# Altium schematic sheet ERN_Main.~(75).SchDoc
size A; SheetNumber: 1; SheetTotal: 4; SPICEModelCacheDBTNACQE: <root> / <DocumentId>DBTNACQE</DocumentId> / </root>
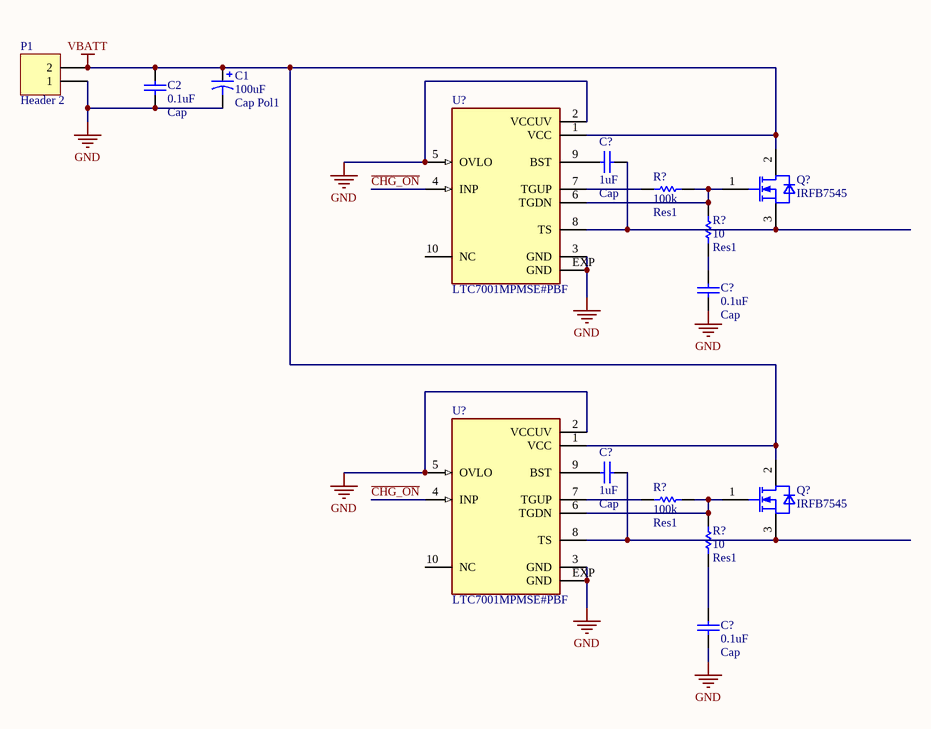
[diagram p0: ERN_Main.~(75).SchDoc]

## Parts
(Parts that share a designator on the sheet are numbered #1, #2 ... from top to bottom, then left to right.)
C1  Cap Pol1  value 100uF  [RB7.6-15]
C2  Cap  value 0.1uF  [RAD-0.3]
C?#1  Cap  value 1uF  [RAD-0.3]
C?#2  Cap  value 0.1uF  [RAD-0.3]
C?#3  Cap  value 1uF  [RAD-0.3]
C?#4  Cap  value 0.1uF  [RAD-0.3]
P1  Header 2  [HDR1X2]
Q?#1  IRFB7545  [IFX-PG-TO220-3-904]
Q?#2  IRFB7545  [IFX-PG-TO220-3-904]
R?#1  Res1  value 100k  [AXIAL-0.3]
R?#2  Res1  value 10  [AXIAL-0.3]
R?#3  Res1  value 100k  [AXIAL-0.3]
R?#4  Res1  value 10  [AXIAL-0.3]
U?#1  LTC7001MPMSE#PBF  [SOP50P490X110-11N]
U?#2  LTC7001MPMSE#PBF  [SOP50P490X110-11N]

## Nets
GND: C1.2 C2.1 C?#2.2 C?#4.2 P1.1 U?#1.2(VCCUV) U?#1.3(GND) U?#1.5(OVLO) U?#1.EXP(GND) U?#2.2(VCCUV) U?#2.3(GND) U?#2.5(OVLO) U?#2.EXP(GND)
VBATT: C1.1 C2.2 P1.2 Q?#1.2(DRAIN) Q?#2.2(DRAIN) U?#1.1(VCC) U?#2.1(VCC)
~{CHG_ON}: U?#1.4(INP) U?#2.4(INP)
NetC?#1_1: C?#1.1 Q?#1.3(SOURCE) U?#1.8(TS)
NetC?#1_2: C?#1.2 U?#1.9(BST)
NetC?#2_1: C?#2.1 R?#2.2
NetC?#3_1: C?#3.1 Q?#2.3(SOURCE) U?#2.8(TS)
NetC?#3_2: C?#3.2 U?#2.9(BST)
NetC?#4_1: C?#4.1 R?#4.2
NetQ?#1_1: Q?#1.1(GATE) R?#1.1 R?#2.1 U?#1.6(TGDN)
NetQ?#2_1: Q?#2.1(GATE) R?#3.1 R?#4.1 U?#2.6(TGDN)
NetR?#1_2: R?#1.2 U?#1.7(TGUP)
NetR?#3_2: R?#3.2 U?#2.7(TGUP)

Not connected (* = marked no-connect by the designer): U?#1 10(NC); U?#2 10(NC)

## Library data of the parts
C1 = Cap Pol1: Polarized Capacitor (Radial)
C2 C?#1-C?#4 = Cap: Capacitor
P1 = Header 2: Header, 2-Pin
Q?#1 Q?#2 = IRFB7545: N-Channel 60V 95A; Insulated-Gate Field-Effect Transistor (IGFET), N-Channel, Enhancement, Body Diode, Pin 1 Gate, 2 Drain, 3 Source, 3 Pins; Manufacturer: Infineon Technologies
R?#1-R?#4 = Res1: Resistor
U?#1 U?#2 = LTC7001MPMSE#PBF: Fast 150V High Side NMOS Static Switch Driver; MF: Analog Devices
